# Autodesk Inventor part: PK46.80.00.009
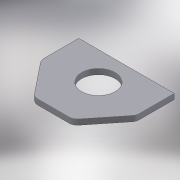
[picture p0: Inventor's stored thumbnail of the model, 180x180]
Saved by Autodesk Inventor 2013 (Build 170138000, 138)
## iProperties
Shininess: 64.0
Length Units: 11269
Angle Units: 11279
Time Units: 11290
Mass Units: 11283
Length Display Precision: 3
Angle Display Precision: 2
Compacted: True
Part Number: PK46.80.00.009
Document SubType Name: Modeling
Created: 2005-01
Material: Steel, Mild
Designer: SAlex
Manufacturer: Standard
Standards Organization: Custom
Density: 7.86 g/cm^3
Mass: 10140.6 g
Surface Area: 1578.47 cm^2
Volume: 1290.15 cm^3
Density: 0.0
Volumn: 0.0
Area: 0.0
PropertySet Name: Model Information
Control State: 0
Master: False
Checked Out: False
Checked Out Date: 2008-10-15
Last Check In Date: 2008-10-15
Author: SAlex
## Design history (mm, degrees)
sketch "Sketch1"
  geometry: L1 (0, 0)-(340, 0); L2 (340, 0)-(340, -135); L3 (340, -135)-(240, -260); L4 (240, -260)-(100, -260); L5 (100, -260)-(0, -135); L6 (0, -135)-(0, 0); C1 r 60 at (170, -100)
  constraints: 12 end point, 2 equal length, 2 parallel, 1 centre point, 1 horizontal, 1 perpendicular, 1 other
  dimensions: "d0" = 340 distance of L1.start L1.end; "d1" = 260 distance between parallel lines of L1 L4; "d2" = 100 horizontal distance of L4.end L5.end; "d3" = 120 diameter of C1; "d4" = 170 distance from line of C1.centre L6 (= 0.5 x d0); "d5" = 100 distance from line of L1 C1.centre; "d6" = 135 distance of L5.end L1.start
extrude "Extrusion1" new body sketch "Sketch1" distance "d7" = 20; taper "d8" = 0 deg
fillet "Fillet1" dims "d9" = 30
body "Solid1"
